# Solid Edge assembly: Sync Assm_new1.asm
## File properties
Author: Sarvanan
Template: sync iso assembly.asm
Last saved by: CADCIM
Revision: 16
Application: Solid Edge
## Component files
casting_new.par
Brasses.par
Bolt.par
Nut.par
Lock Nut.par
Bolt_mir.par
Nut_mir.par
Lock Nut_mir.par
cap.par
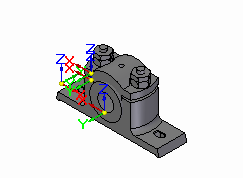
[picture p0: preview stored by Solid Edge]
